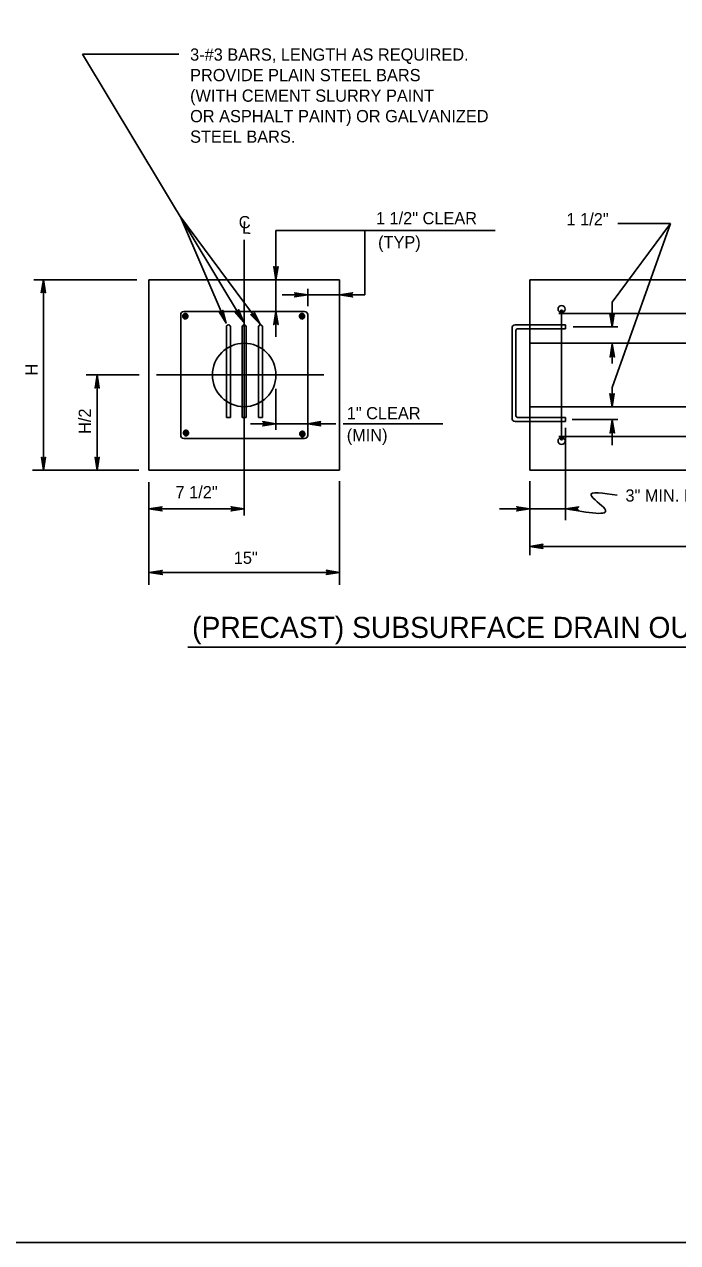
# Model space of a CAD drawing. Extents: x 638877 to 639960, y 297341 to 299123.
# Drawn here: x 639335.5 to 639496, y 298544.3 to 298843.4 of the extents above; entities that cross this region are included whole.
import ezdxf

# ---------------------------------------------------------------- set-up
doc = ezdxf.new("R2010")
doc.units = 0
for name, color, linetype in [('1', 7, 'Continuous'), ('2', 7, 'Continuous'), ('3', 7, 'Continuous')]:
    doc.layers.add(name, color=color, linetype=linetype)

msp = doc.modelspace()

# ---------------------------------------------------------------- linework, layer by layer
at = {"layer": '1'}
for p, q in [((639397.33, 298780.71), (639397.33, 298792.8)), ((639389.53, 298722.82), (639389.53, 298790.46)), ((639397.33, 298772.91), (639397.33, 298780.71)), ((639470.35, 298769.13), (639481.33, 298769.13)), ((639363.76, 298757.31), (639350.68, 298757.31)), ((639409.11, 298757.31), (639367.96, 298757.31)), ((639470.14, 298746.42), (639481.33, 298746.42))]:
    msp.add_line(p, q, dxfattribs=at)
msp.add_lwpolyline([(639703.19, 298544.28), (639703.19, 299108.28), (638917.19, 299108.28), (638917.19, 298544.28), (639703.19, 298544.28), (639703.19, 298570.64), (639503.19, 298570.64), (639503.19, 298635.32), (639703.19, 298635.32), (639703.19, 298664.28), (639503.19, 298664.28), (639503.19, 298544.28), (639581.99, 298544.28), (639581.99, 298570.64), (639581.99, 298544.28), (639658.99, 298544.28), (639658.99, 298570.64), (639658.99, 298558.33), (639703.19, 298558.33)], dxfattribs=at)
for centre, radius in [((639467.5, 298773.49), 0.864), ((639467.53, 298772.91), 0.289), ((639467.5, 298741.12), 0.864), ((639467.53, 298741.71), 0.289), ((639467.53, 298741.71), 0.289)]:
    msp.add_circle(centre, radius, dxfattribs=at)
for centre, radius, start, end in [((639374.71, 298772.13), 0.78, 90, 180), ((639404.35, 298772.13), 0.78, 0, 90), ((639456.12, 298768.83), 0.78, 90, 180), ((639456.7, 298768.25), 0.39, 90, 180), ((639456.12, 298746.71), 0.78, 180, 270), ((639456.7, 298747.3), 0.39, 180, 270), ((639374.71, 298742.49), 0.78, 180, 270), ((639404.35, 298742.49), 0.78, 270, 0)]:
    msp.add_arc(centre, radius, start, end, dxfattribs=at)
msp.add_spline([(639481.2, 298727.8), (639474.76, 298727.8), (639478.12, 298724.44), (639468.5, 298724.44)], degree=3, dxfattribs=at)
at = {"layer": '2'}
for p, q in [((639389.34, 298770.33), (639349.81, 298836.09)), ((639349.81, 298836.09), (639373.47, 298836.09)), ((639385.1, 298770.04), (639373.9, 298796.18)), ((639393.48, 298769.82), (639373.9, 298796.18)), ((639479.91, 298775.22), (639494.24, 298794.51)), ((639479.91, 298754.26), (639494.24, 298794.51)), ((639419.17, 298776.97), (639419.17, 298792.8)), ((639363.12, 298780.71), (639337.81, 298780.71)), ((639340.2, 298733.91), (639340.2, 298780.71)), ((639412.93, 298780.71), (639366.13, 298780.71)), ((639366.13, 298780.71), (639366.13, 298733.91)), ((639412.93, 298733.91), (639412.93, 298780.71)), ((639600.13, 298780.71), (639459.73, 298780.71)), ((639459.73, 298780.71), (639459.73, 298733.91)), ((639405.13, 298774.23), (639405.13, 298778.47)), ((639404.35, 298772.91), (639374.71, 298772.91)), ((639467.53, 298772.91), (639467.53, 298741.71)), ((639479.91, 298769.13), (639479.91, 298775.22)), ((639373.93, 298772.13), (639373.93, 298742.49)), ((639405.13, 298742.49), (639405.13, 298772.13)), ((639593.28, 298772.42), (639466.82, 298772.42)), ((639385.16, 298746.91), (639385.16, 298769.13)), ((639386.13, 298746.91), (639386.13, 298769.13)), ((639389.04, 298746.91), (639389.04, 298769.13)), ((639390.01, 298746.91), (639390.01, 298769.13)), ((639393.03, 298746.91), (639393.03, 298769.13)), ((639394, 298746.91), (639394, 298769.13)), ((639455.34, 298746.71), (639455.34, 298768.83)), ((639459.71, 298769.61), (639456.12, 298769.61)), ((639456.31, 298747.3), (639456.31, 298768.25)), ((639459.64, 298768.64), (639456.7, 298768.64)), ((639468.5, 298768.64), (639459.64, 298768.64)), ((639468.5, 298769.61), (639459.71, 298769.61)), ((639468.5, 298768.64), (639468.5, 298769.61)), ((639600.13, 298765.11), (639459.73, 298765.11)), ((639479.91, 298760.14), (639479.91, 298765.11)), ((639397.33, 298753.91), (639397.33, 298743.83)), ((639479.91, 298749.51), (639479.91, 298754.26)), ((639600.13, 298749.51), (639459.73, 298749.51)), ((639385.16, 298746.91), (639386.13, 298746.91)), ((639389.04, 298746.91), (639390.01, 298746.91)), ((639393.03, 298746.91), (639394, 298746.91)), ((639459.64, 298745.93), (639456.12, 298745.93)), ((639459.64, 298746.91), (639456.7, 298746.91)), ((639468.5, 298746.91), (639459.64, 298746.91)), ((639468.5, 298745.93), (639459.71, 298745.93)), ((639468.5, 298745.93), (639468.5, 298746.91)), ((639479.91, 298740.11), (639479.91, 298746.42)), ((639468.5, 298721.63), (639468.5, 298744.32)), ((639404.35, 298741.71), (639374.71, 298741.71)), ((639593.28, 298742.19), (639466.82, 298742.19)), ((639363.63, 298733.91), (639337.49, 298733.91)), ((639412.93, 298733.91), (639366.13, 298733.91)), ((639600.13, 298733.91), (639459.73, 298733.91)), ((639366.13, 298705.82), (639366.13, 298730.99)), ((639412.93, 298705.82), (639412.93, 298731.25)), ((639459.73, 298713.09), (639459.73, 298731.25)), ((639468.5, 298724.44), (639452.29, 298724.44)), ((639600.13, 298715.23), (639459.73, 298715.23)), ((639412.93, 298708.83), (639366.19, 298708.83))]:
    msp.add_line(p, q, dxfattribs=at)
for points in [[(639384.24, 298773.01), (639384.09, 298772.81), (639385.1, 298770.04), (639384.24, 298773.01), (639384.31, 298773.21), (639385.1, 298770.04), (639383.8, 298772.69), (639383.56, 298772.71), (639385.1, 298770.04), (639383.36, 298772.8), (639383.56, 298772.71)], [(639388.1, 298773.16), (639387.96, 298772.95), (639389.34, 298770.33), (639388.1, 298773.16), (639388.13, 298773.37), (639389.34, 298770.33), (639387.7, 298772.79), (639387.46, 298772.77), (639389.34, 298770.33), (639387.24, 298772.84), (639387.46, 298772.77)], [(639391.96, 298772.52), (639391.84, 298772.29), (639393.48, 298769.82), (639391.96, 298772.52), (639391.97, 298772.72), (639393.48, 298769.82), (639391.6, 298772.1), (639391.36, 298772.06), (639393.48, 298769.82), (639391.14, 298772.11), (639391.36, 298772.06)]]:
    msp.add_lwpolyline(points, dxfattribs=at)
msp.add_circle((639389.53, 298757.31), 7.8, dxfattribs=at)
for centre in [(639385.64, 298769.13), (639389.53, 298769.13), (639393.51, 298769.13)]:
    msp.add_arc(centre, 0.486, 359.692, 180, dxfattribs=at)
for points in [[(639375.07, 298771.74), (639375.13, 298771.7), (639375.13, 298771.64), (639375.02, 298771.64), (639374.98, 298771.73), (639375.02, 298771.85), (639375.13, 298771.84), (639375.19, 298771.78), (639375.2, 298771.64), (639375.13, 298771.56), (639375.03, 298771.51), (639374.9, 298771.58), (639374.87, 298771.72), (639374.91, 298771.88), (639375, 298771.96), (639375.16, 298771.95), (639375.26, 298771.87), (639375.29, 298771.73), (639375.27, 298771.61), (639375.21, 298771.5), (639375.11, 298771.46), (639374.98, 298771.43), (639374.86, 298771.46), (639374.78, 298771.59), (639374.75, 298771.77), (639374.83, 298771.98), (639374.96, 298772.08), (639375.13, 298772.08), (639375.28, 298772.01), (639375.38, 298771.87), (639375.39, 298771.64), (639375.31, 298771.49), (639375.17, 298771.39), (639375.02, 298771.33), (639374.85, 298771.36), (639374.73, 298771.49), (639374.66, 298771.68), (639374.7, 298771.97), (639374.85, 298772.16), (639375.06, 298772.2), (639375.26, 298772.16), (639375.42, 298772.04), (639375.47, 298771.86), (639375.47, 298771.59), (639375.35, 298771.37), (639375.2, 298771.27), (639375.02, 298771.24), (639374.87, 298771.27), (639374.71, 298771.33), (639374.59, 298771.5), (639374.56, 298771.79), (639374.62, 298772.04), (639374.78, 298772.22), (639374.97, 298772.3), (639375.2, 298772.28), (639375.42, 298772.2), (639375.52, 298772.06), (639375.6, 298771.81), (639375.56, 298771.55), (639375.49, 298771.36), (639375.35, 298771.23), (639375.19, 298771.15), (639375.02, 298771.15), (639374.85, 298771.16), (639374.69, 298771.21), (639374.59, 298771.3), (639374.51, 298771.44), (639374.47, 298771.58), (639374.44, 298771.72), (639374.47, 298771.9), (639374.52, 298772.08), (639374.63, 298772.24), (639374.76, 298772.34), (639374.93, 298772.4), (639375.09, 298772.43), (639375.27, 298772.39), (639375.42, 298772.31), (639375.55, 298772.19), (639375.64, 298772.04), (639375.69, 298771.87), (639375.69, 298771.69), (639375.65, 298771.48), (639375.55, 298771.3), (639375.44, 298771.19), (639375.31, 298771.1), (639375.16, 298771.06), (639374.96, 298771.06), (639374.9, 298771.07), (639374.74, 298771.15), (639374.62, 298771.27)], [(639403.73, 298771.74), (639403.8, 298771.7), (639403.79, 298771.64), (639403.69, 298771.64), (639403.64, 298771.73), (639403.69, 298771.85), (639403.79, 298771.84), (639403.85, 298771.78), (639403.86, 298771.64), (639403.8, 298771.56), (639403.69, 298771.51), (639403.56, 298771.58), (639403.54, 298771.72), (639403.58, 298771.88), (639403.67, 298771.96), (639403.82, 298771.95), (639403.92, 298771.87), (639403.95, 298771.73), (639403.93, 298771.61), (639403.87, 298771.5), (639403.77, 298771.46), (639403.65, 298771.43), (639403.53, 298771.46), (639403.45, 298771.59), (639403.41, 298771.77), (639403.49, 298771.98), (639403.62, 298772.08), (639403.8, 298772.08), (639403.94, 298772.01), (639404.05, 298771.87), (639404.06, 298771.64), (639403.98, 298771.49), (639403.84, 298771.39), (639403.69, 298771.33), (639403.52, 298771.36), (639403.39, 298771.49), (639403.32, 298771.68), (639403.36, 298771.97), (639403.51, 298772.16), (639403.72, 298772.2), (639403.92, 298772.16), (639404.08, 298772.04), (639404.14, 298771.86), (639404.13, 298771.59), (639404.02, 298771.37), (639403.86, 298771.27), (639403.68, 298771.24), (639403.54, 298771.27), (639403.37, 298771.33), (639403.25, 298771.5), (639403.22, 298771.79), (639403.28, 298772.04), (639403.44, 298772.22), (639403.63, 298772.3), (639403.86, 298772.28), (639404.08, 298772.2), (639404.18, 298772.06), (639404.26, 298771.81), (639404.23, 298771.55), (639404.15, 298771.36), (639404.01, 298771.23), (639403.85, 298771.15), (639403.69, 298771.15), (639403.52, 298771.16), (639403.35, 298771.21), (639403.25, 298771.3), (639403.17, 298771.44), (639403.13, 298771.58), (639403.1, 298771.72), (639403.14, 298771.9), (639403.18, 298772.08), (639403.29, 298772.24), (639403.43, 298772.34), (639403.59, 298772.4), (639403.76, 298772.43), (639403.93, 298772.39), (639404.08, 298772.31), (639404.21, 298772.19), (639404.3, 298772.04), (639404.35, 298771.87), (639404.36, 298771.69), (639404.31, 298771.48), (639404.21, 298771.3), (639404.11, 298771.19), (639403.97, 298771.1), (639403.83, 298771.06), (639403.62, 298771.06), (639403.56, 298771.07), (639403.4, 298771.15), (639403.28, 298771.27)], [(639375.23, 298743.08), (639375.3, 298743.04), (639375.3, 298742.98), (639375.19, 298742.98), (639375.14, 298743.07), (639375.19, 298743.18), (639375.3, 298743.18), (639375.36, 298743.12), (639375.36, 298742.98), (639375.3, 298742.9), (639375.2, 298742.85), (639375.07, 298742.92), (639375.04, 298743.05), (639375.08, 298743.21), (639375.17, 298743.3), (639375.33, 298743.29), (639375.43, 298743.21), (639375.46, 298743.07), (639375.44, 298742.94), (639375.38, 298742.84), (639375.28, 298742.79), (639375.15, 298742.77), (639375.03, 298742.8), (639374.95, 298742.92), (639374.92, 298743.11), (639375, 298743.31), (639375.13, 298743.42), (639375.3, 298743.42), (639375.45, 298743.35), (639375.55, 298743.21), (639375.56, 298742.98), (639375.48, 298742.82), (639375.34, 298742.72), (639375.19, 298742.67), (639375.02, 298742.69), (639374.9, 298742.82), (639374.83, 298743.01), (639374.87, 298743.31), (639375.02, 298743.49), (639375.23, 298743.53), (639375.43, 298743.49), (639375.58, 298743.37), (639375.64, 298743.2), (639375.64, 298742.92), (639375.52, 298742.71), (639375.36, 298742.61), (639375.19, 298742.58), (639375.04, 298742.6), (639374.88, 298742.67), (639374.76, 298742.84), (639374.73, 298743.12), (639374.79, 298743.38), (639374.95, 298743.56), (639375.14, 298743.64), (639375.37, 298743.61), (639375.59, 298743.53), (639375.69, 298743.39), (639375.76, 298743.14), (639375.73, 298742.89), (639375.66, 298742.7), (639375.52, 298742.56), (639375.36, 298742.49), (639375.19, 298742.49), (639375.02, 298742.5), (639374.86, 298742.54), (639374.76, 298742.63), (639374.68, 298742.77), (639374.64, 298742.92), (639374.61, 298743.05), (639374.64, 298743.24), (639374.69, 298743.42), (639374.79, 298743.57), (639374.93, 298743.68), (639375.1, 298743.74), (639375.26, 298743.76), (639375.44, 298743.72), (639375.58, 298743.65), (639375.72, 298743.52), (639375.8, 298743.37), (639375.85, 298743.21), (639375.86, 298743.03), (639375.82, 298742.81), (639375.72, 298742.63), (639375.61, 298742.52), (639375.48, 298742.43), (639375.33, 298742.4), (639375.13, 298742.4), (639375.07, 298742.41), (639374.91, 298742.49), (639374.79, 298742.6)], [(639403.81, 298742.83), (639403.88, 298742.79), (639403.88, 298742.73), (639403.77, 298742.72), (639403.72, 298742.82), (639403.77, 298742.93), (639403.88, 298742.92), (639403.93, 298742.86), (639403.94, 298742.73), (639403.88, 298742.64), (639403.78, 298742.6), (639403.65, 298742.66), (639403.62, 298742.8), (639403.66, 298742.96), (639403.75, 298743.05), (639403.91, 298743.04), (639404.01, 298742.96), (639404.04, 298742.82), (639404.02, 298742.69), (639403.96, 298742.59), (639403.86, 298742.54), (639403.73, 298742.51), (639403.61, 298742.55), (639403.53, 298742.67), (639403.5, 298742.86), (639403.57, 298743.06), (639403.7, 298743.16), (639403.88, 298743.16), (639404.03, 298743.1), (639404.13, 298742.96), (639404.14, 298742.73), (639404.06, 298742.57), (639403.92, 298742.47), (639403.77, 298742.42), (639403.6, 298742.44), (639403.48, 298742.57), (639403.4, 298742.76), (639403.45, 298743.06), (639403.6, 298743.24), (639403.8, 298743.28), (639404.01, 298743.24), (639404.16, 298743.12), (639404.22, 298742.94), (639404.22, 298742.67), (639404.1, 298742.46), (639403.94, 298742.35), (639403.77, 298742.33), (639403.62, 298742.35), (639403.45, 298742.41), (639403.34, 298742.59), (639403.31, 298742.87), (639403.37, 298743.12), (639403.53, 298743.31), (639403.71, 298743.38), (639403.95, 298743.36), (639404.17, 298743.28), (639404.27, 298743.14), (639404.34, 298742.89), (639404.31, 298742.63), (639404.24, 298742.44), (639404.1, 298742.31), (639403.94, 298742.24), (639403.77, 298742.24), (639403.6, 298742.24), (639403.44, 298742.29), (639403.34, 298742.38), (639403.26, 298742.52), (639403.22, 298742.66), (639403.19, 298742.8), (639403.22, 298742.98), (639403.27, 298743.16), (639403.37, 298743.32), (639403.51, 298743.43), (639403.68, 298743.48), (639403.84, 298743.51), (639404.02, 298743.47), (639404.16, 298743.4), (639404.29, 298743.27), (639404.38, 298743.12), (639404.43, 298742.96), (639404.44, 298742.77), (639404.4, 298742.56), (639404.29, 298742.38), (639404.19, 298742.27), (639404.06, 298742.18), (639403.91, 298742.15), (639403.7, 298742.15), (639403.65, 298742.15), (639403.49, 298742.24), (639403.36, 298742.35)]]:
    msp.add_spline(points, degree=3, dxfattribs=at)
at = {"layer": '3'}
for p, q in [((639494.24, 298794.51), (639481.3, 298794.51)), ((639419.17, 298792.8), (639397.33, 298792.8)), ((639451.22, 298792.8), (639419.17, 298792.8)), ((639405.15, 298776.97), (639398.9, 298776.97)), ((639412.93, 298776.97), (639405.13, 298776.97)), ((639419.17, 298776.97), (639412.93, 298776.97)), ((639397.33, 298772.91), (639397.33, 298766.66)), ((639353.41, 298733.91), (639353.41, 298757.31)), ((639397.33, 298745.33), (639391.08, 298745.33)), ((639405.13, 298745.33), (639395.97, 298745.33)), ((639412.01, 298745.33), (639405.13, 298745.33)), ((639438.36, 298745.33), (639413.85, 298745.33)), ((639389.53, 298724.44), (639366.13, 298724.44)), ((639375.71, 298690.46), (639588.62, 298690.46))]:
    msp.add_line(p, q, dxfattribs=at)
for points in [[(639396.94, 298783.78), (639397.16, 298783.66), (639397.33, 298780.71), (639396.94, 298783.78), (639396.81, 298783.93), (639397.33, 298780.71), (639397.47, 298783.66), (639397.69, 298783.77), (639397.33, 298780.71), (639397.84, 298783.93), (639397.69, 298783.77)], [(639339.82, 298777.64), (639340.04, 298777.75), (639340.2, 298780.71), (639339.82, 298777.64), (639339.68, 298777.48), (639340.2, 298780.71), (639340.35, 298777.75), (639340.57, 298777.65), (639340.2, 298780.71), (639340.72, 298777.48), (639340.57, 298777.65)], [(639402.08, 298777.35), (639402.19, 298777.13), (639405.15, 298776.97), (639402.08, 298777.35), (639401.92, 298777.49), (639405.15, 298776.97), (639402.19, 298776.82), (639402.09, 298776.6), (639405.15, 298776.97), (639401.92, 298776.46), (639402.09, 298776.6)], [(639416, 298777.35), (639415.88, 298777.13), (639412.93, 298776.97), (639416, 298777.35), (639416.15, 298777.49), (639412.93, 298776.97), (639415.88, 298776.82), (639415.99, 298776.6), (639412.93, 298776.97), (639416.15, 298776.46), (639415.99, 298776.6)], [(639396.94, 298769.84), (639397.16, 298769.95), (639397.33, 298772.91), (639396.94, 298769.84), (639396.81, 298769.68), (639397.33, 298772.91), (639397.47, 298769.95), (639397.69, 298769.85), (639397.33, 298772.91), (639397.84, 298769.68), (639397.69, 298769.85)], [(639480.29, 298772.2), (639480.07, 298772.08), (639479.91, 298769.13), (639480.29, 298772.2), (639480.43, 298772.35), (639479.91, 298769.13), (639479.76, 298772.08), (639479.54, 298772.19), (639479.91, 298769.13), (639479.39, 298772.35), (639479.54, 298772.19)], [(639479.58, 298761.88), (639479.8, 298761.99), (639479.96, 298764.95), (639479.58, 298761.88), (639479.44, 298761.72), (639479.96, 298764.95), (639480.11, 298761.99), (639480.33, 298761.89), (639479.96, 298764.95), (639480.48, 298761.72), (639480.33, 298761.89)], [(639353.02, 298754.24), (639353.24, 298754.35), (639353.41, 298757.31), (639353.02, 298754.24), (639352.89, 298754.08), (639353.41, 298757.31), (639353.55, 298754.35), (639353.77, 298754.25), (639353.41, 298757.31), (639353.92, 298754.08), (639353.77, 298754.25)], [(639480.29, 298752.58), (639480.07, 298752.46), (639479.91, 298749.51), (639480.29, 298752.58), (639480.43, 298752.73), (639479.91, 298749.51), (639479.76, 298752.46), (639479.54, 298752.57), (639479.91, 298749.51), (639479.39, 298752.73), (639479.54, 298752.57)], [(639394.26, 298745.72), (639394.37, 298745.5), (639397.33, 298745.33), (639394.26, 298745.72), (639394.1, 298745.85), (639397.33, 298745.33), (639394.37, 298745.19), (639394.27, 298744.97), (639397.33, 298745.33), (639394.1, 298744.82), (639394.27, 298744.97)], [(639408.2, 298745.72), (639408.08, 298745.5), (639405.13, 298745.33), (639408.2, 298745.72), (639408.35, 298745.85), (639405.13, 298745.33), (639408.08, 298745.19), (639408.19, 298744.97), (639405.13, 298745.33), (639408.35, 298744.82), (639408.19, 298744.97)], [(639479.58, 298743.19), (639479.8, 298743.3), (639479.96, 298746.26), (639479.58, 298743.19), (639479.44, 298743.03), (639479.96, 298746.26), (639480.11, 298743.31), (639480.33, 298743.2), (639479.96, 298746.26), (639480.48, 298743.03), (639480.33, 298743.2)], [(639340.59, 298736.98), (639340.37, 298736.86), (639340.2, 298733.91), (639340.59, 298736.98), (639340.72, 298737.13), (639340.2, 298733.91), (639340.06, 298736.86), (639339.84, 298736.97), (639340.2, 298733.91), (639339.69, 298737.13), (639339.84, 298736.97)], [(639353.79, 298736.98), (639353.57, 298736.86), (639353.41, 298733.91), (639353.79, 298736.98), (639353.93, 298737.13), (639353.41, 298733.91), (639353.26, 298736.86), (639353.04, 298736.97), (639353.41, 298733.91), (639352.89, 298737.13), (639353.04, 298736.97)], [(639369.2, 298724.05), (639369.08, 298724.28), (639366.13, 298724.44), (639369.2, 298724.05), (639369.35, 298723.92), (639366.13, 298724.44), (639369.08, 298724.58), (639369.19, 298724.81), (639366.13, 298724.44), (639369.35, 298724.95), (639369.19, 298724.81)], [(639386.46, 298724.82), (639386.57, 298724.6), (639389.53, 298724.44), (639386.46, 298724.82), (639386.3, 298724.96), (639389.53, 298724.44), (639386.57, 298724.29), (639386.47, 298724.07), (639389.53, 298724.44), (639386.3, 298723.93), (639386.47, 298724.07)], [(639456.66, 298724.82), (639456.77, 298724.6), (639459.73, 298724.44), (639456.66, 298724.82), (639456.5, 298724.96), (639459.73, 298724.44), (639456.77, 298724.29), (639456.67, 298724.07), (639459.73, 298724.44), (639456.5, 298723.93), (639456.67, 298724.07)], [(639471.57, 298724.05), (639471.46, 298724.28), (639468.5, 298724.44), (639471.57, 298724.05), (639471.73, 298723.92), (639468.5, 298724.44), (639471.46, 298724.58), (639471.56, 298724.81), (639468.5, 298724.44), (639471.73, 298724.95), (639471.56, 298724.81)], [(639462.8, 298714.85), (639462.68, 298715.07), (639459.73, 298715.23), (639462.8, 298714.85), (639462.95, 298714.71), (639459.73, 298715.23), (639462.68, 298715.38), (639462.79, 298715.6), (639459.73, 298715.23), (639462.95, 298715.74), (639462.79, 298715.6)], [(639369.26, 298708.45), (639369.14, 298708.67), (639366.19, 298708.83), (639369.26, 298708.45), (639369.41, 298708.31), (639366.19, 298708.83), (639369.14, 298708.98), (639369.25, 298709.2), (639366.19, 298708.83), (639369.41, 298709.34), (639369.25, 298709.2)], [(639409.86, 298709.22), (639409.97, 298708.99), (639412.93, 298708.83), (639409.86, 298709.22), (639409.7, 298709.35), (639412.93, 298708.83), (639409.97, 298708.69), (639409.87, 298708.46), (639412.93, 298708.83), (639409.7, 298708.32), (639409.87, 298708.46)]]:
    msp.add_lwpolyline(points, dxfattribs=at)

# ---------------------------------------------------------------- texts
at = {"layer": '1'}
for s, height, p in [('3-#3 BARS, LENGTH AS REQUIRED. ', 2.9999, (639376.24, 298834.48)), ('PROVIDE PLAIN STEEL BARS', 2.9999, (639376.24, 298829.44)), ('(WITH CEMENT SLURRY PAINT ', 2.9999, (639376.24, 298824.4)), ('OR ASPHALT PAINT) OR GALVANIZED', 2.9999, (639376.24, 298819.37)), ('STEEL BARS.', 2.9999, (639376.24, 298814.33)), ('7 1/2"', 3, (639372.66, 298727.04)), ('15"', 3, (639386.97, 298710.94))]:
    msp.add_text(s, height=height, dxfattribs=at).set_placement(p)
for s, rotation, p in [('C', 5, (639388.32, 298793.2)), ('L', 357, (639388.96, 298792.05))]:
    msp.add_text(s, height=3, rotation=rotation, dxfattribs=at).set_placement(p)
at = {"layer": '3'}
for s, height, p in [('1 1/2" CLEAR', 2.9999, (639421.9, 298794.3)), ('1 1/2"', 3, (639468.73, 298794.05)), ('(TYP)', 3, (639422.43, 298788.41)), ('1" CLEAR', 3, (639414.73, 298746.44)), ('(MIN)', 3, (639414.73, 298741.06)), ('3" MIN. EMBEDMENT', 2.9999, (639483.21, 298726.22)), ('(PRECAST) SUBSURFACE DRAIN OUTLET ENDWALL', 5.1858, (639376.74, 298692.75))]:
    msp.add_text(s, height=height, dxfattribs=at).set_placement(p)
for s, p in [('H', (639338.77, 298757.16)), ('H/2', (639351.86, 298742.83))]:
    msp.add_text(s, height=3, rotation=90, dxfattribs=at).set_placement(p)

doc.saveas('drawing.dxf')
